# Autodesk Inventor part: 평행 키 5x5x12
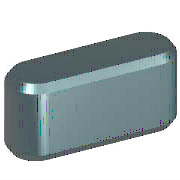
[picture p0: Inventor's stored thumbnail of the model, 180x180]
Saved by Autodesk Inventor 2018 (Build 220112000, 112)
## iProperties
IsCustomPart: 1
Created: 2012-02
Part Number: 평행 키 5x5x12
Material: 강철, 연강
Description: 평행 키
Document SubType Name: Modeling
Standard: JIS B 1301
Designer: mdu-01
Standards Organization: JIS
Language: ko-KR
Size Designation: 5x5x12
Categories: <MemberInstance><Categories><Category DisplayName="샤프트 부품" InternalName="7f7aeb1f-a693-4053-b835-cee3144e0d98" Mnemonic="SHFT"><Category DisplayName="키" Interna
Density: 1 g/cm^3
Appearance: 강철
Author: mdu-01
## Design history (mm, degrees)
workplane "Work Plane1"
workplane "Work Plane2"
sketch "스케치1"
  geometry: L1 (2.5, 2.5)-(9.5, 2.5); L2 (9.5, -2.5)-(2.5, -2.5); L3 (0, 9.4)-(0, -7.4) reference; L4 (-5, 0)-(30, 0) reference; L5 (12, 0)-(12, 7); A1 r 2.5 centre (2.5, 0) between (2.5, 2.5) and (2.5, -2.5); A2 r 2.5 centre (9.5, 0) between (9.5, -2.5) and (9.5, 2.5)
  constraints: 6 end point, 5 point on circle, 4 tangent, 3 point on line, 2 centre point, 1 horizontal, 1 parallel, 1 perpendicular
  dimensions: "d0" = 2.5 radius of A1 (= 0.5 x PB); "d13" = 2.5 radius of A2 (= 0.5 x PB); "d14" = 12 distance between parallel lines of L5 L3 (= NLG)
extrude "본체1" new body sketch "스케치1" taper "d3" = 0 deg; stored distance "d4" = 10
workplane "Work Plane3"
body "Solid1"
chamfer "모따기1" distance "d8" = 0.4 (= PHH); stored, may be unused: second distance "d9" = 0.4 (= PHH), angle "d15" = 45 deg
other parameters: "d1" = -3 (= -PNT), "d2" = 2 (= PH - PNT), "NLG" = 12 [user parameter; used in 3 equation terms], "PB" = 5 [user parameter; used in 2 equation terms], "PNT" = 3 [user parameter; used in 2 equation terms], "PH" = 5 [user parameter; used in 1 equation term], "PHH" = 0.4 [user parameter; used in 2 equation terms], "d10" = 0, "d16" = 0, "d17" = 0, "d18" = 0, "WDMIN" = 12 [user parameter], "PLB2" = 12 (= NLG) [user parameter], "WDMAX" = 17 [user parameter], "PLB1" = 12 (= NLG) [user parameter], "RR" = 0.16 [user parameter], "PUEB" = 2.3 [user parameter]
